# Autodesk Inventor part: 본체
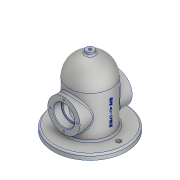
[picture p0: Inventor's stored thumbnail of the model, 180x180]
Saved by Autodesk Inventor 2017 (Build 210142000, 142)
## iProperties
Created: 2019-11
Part Number: 본체
Material: Aluminum 6061
Document SubType Name: Modeling
Designer: 1-06-lg
Density: 2.7 g/cm^3
Appearance: Aluminum - Flat
Mass: 1106.12 g
Surface Area: 883.25 cm^2
Volume: 409.674 cm^3
Author: 1-06-lg
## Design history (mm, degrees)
sketch "Sketch5"
  geometry: L1 (0, 0)-(90, 0); L2 (90, 0)-(90, -40); L3 (90, -40)-(0, -40); L4 (0, -40)-(0, 0); L5 (90, 0)-(130, 0); A1 r 40 centre (90, 0) between (50, 0) and (130, 0)
  constraints: 10 end point, 2 horizontal, 2 parallel, 2 point on circle, 1 centre point, 1 perpendicular, 1 point on line
  dimensions: "d6" = 80 diameter of L3 L1; "d7" = 90 distance of L1.start L1.end; "d8" = 80 diameter of A1
revolve "Revolution2" sketch "Sketch5" stored, may be unused: angle "d9" = 90 deg
sketch "Sketch6"
  geometry: C1 r 70 at (0, 0); 1 further point
  constraints: 1 centre point, 1 coincident
  dimensions: "d10" = 140 diameter of C1
extrude "Extrusion1" join sketch "Sketch6" distance "d11" = 10; taper "d12" = 0 deg
sketch "Sketch7"
  geometry: L1 (0, 0)-(0, 50); C1 r 31 at (0, 50)
  constraints: 2 end point, 1 centre point, 1 coincident, 1 vertical
  dimensions: "d13" = 50 distance of L1.start L1.end; "d14" = 62 diameter of C1
extrude "Extrusion2" join sketch "Sketch7" stored distance "d15" = 100; taper "d16" = 0 deg
sketch "Sketch8"
  geometry: L1 (0, 0)-(90, 0); L2 (90, 0)-(90, -30); L3 (90, -30)-(0, -30); L4 (0, -30)-(0, 0); L5 (90, 0)-(120, 0); A1 r 30 centre (90, 0) between (60, 0) and (120, 0)
  constraints: 10 end point, 2 horizontal, 2 parallel, 2 point on circle, 1 centre point, 1 perpendicular, 1 point on line
  dimensions: "d17" = 60 diameter of L3 L1; "d18" = 90 distance of L1.start L1.end; "d19" = 60 diameter of A1
revolve "Revolution3" sketch "Sketch8" stored, may be unused: angle "d20" = 90 deg
sketch "Sketch9"
  geometry: C1 r 31 at (0, 0) reference; C2 r 20 at (0, 0); 1 further point
  constraints: 1 centre point, 1 coincident
  dimensions: "d21" = 40 diameter of C2
extrude "Extrusion3" cut sketch "Sketch9" distance "d22" = 15; taper "d23" = 0 deg
sketch "Sketch10"
  geometry: C1 r 20 at (0, 0) reference; C2 r 16.5 at (0, 0); 1 further point
  constraints: 1 centre point, 1 coincident
  dimensions: "d24" = 33 diameter of C2
extrude "Extrusion4" cut sketch "Sketch10" stored distance "d25" = 15; taper "d26" = 0 deg
sketch "Sketch11" dims "d27" = 52
  geometry: L1 (0, 0)-(0, 26); C1 r 31 at (0, 0) reference; 2 further points
  constraints: 2 coincident, 2 end point, 1 vertical, 1 vertical alignment, 2 other
hole "Hole1" sketch "Sketch11" at (0, 26) diameter "d28" = 3.242; stored, may be unused: countersink angle "d32" = 90 deg, drill point angle "d34" = 118 deg; dims "d29" = 8, "d30" = 4, "d31" = 2, "d33" = 10
pattern_circular "Circular Pattern1" dims angle "d36" = 360 deg
mirror "Mirror2"
workplane "Work Plane1"
sketch "Sketch12"
  geometry: C1 r 7.5 at (0, 0); 1 further point
  constraints: 1 centre point, 1 coincident
  dimensions: "d39" = 15 diameter of C1
extrude "Extrusion5" join sketch "Sketch12" stored distance "d40" = 15; taper "d41" = 0 deg
sketch "Sketch13"
  geometry: C1 r 7.5 at (0, 0) reference; 1 further point
  constraints: 1 coincident
hole "Hole2" sketch "Sketch13" at (0, 0) diameter "d42" = 5.188; stored, may be unused: countersink angle "d46" = 90 deg, drill point angle "d48" = 118 deg; dims "d43" = 12, "d44" = 4, "d45" = 2, "d47" = 16
sketch "Sketch14" dims "d49" = 110
  geometry: L1 (0, 0)-(55, 0); C1 r 40 at (0, 0) reference; C2 r 4.5 at (55, 0)
  constraints: 2 coincident, 2 end point, 1 centre point, 1 horizontal, 1 horizontal alignment, 2 other
  dimensions: "d50" = 9 diameter of C2
extrude "Extrusion6" cut sketch "Sketch14" stored distance "d51" = 15; taper "d52" = 0 deg
pattern_circular "Circular Pattern2" dims angle "d54" = 360 deg
workplane "Work Plane2"
sketch "Sketch15"
  geometry: L1 (0, 70)-(0, -70) reference; L2 (0, 70)-(10, 70) reference; 2 further points
  constraints: 1 other
  dimensions: "d57" = 50 distance from line of L1 point (50, 0)
emboss "Emboss1" sketch "Sketch15" dims "d6" = 80, "d7" = 90, "d8" = 80, "d17" = 60, "d18" = 90, "d19" = 60, "d59" = 0.5, "d60" = 0
fillet "Fillet1" dims "d61" = 3
chamfer "Chamfer1" distance "d62" = 1; stored, may be unused: second distance "d63" = 2, angle "d64" = 45 deg
fillet "Fillet2" dims "d65" = 0.3
fillet "Fillet3" dims "d66" = 3
fillet "Fillet4" dims "d67" = 3
body "Solid2"
other parameters: "d38" = 135
